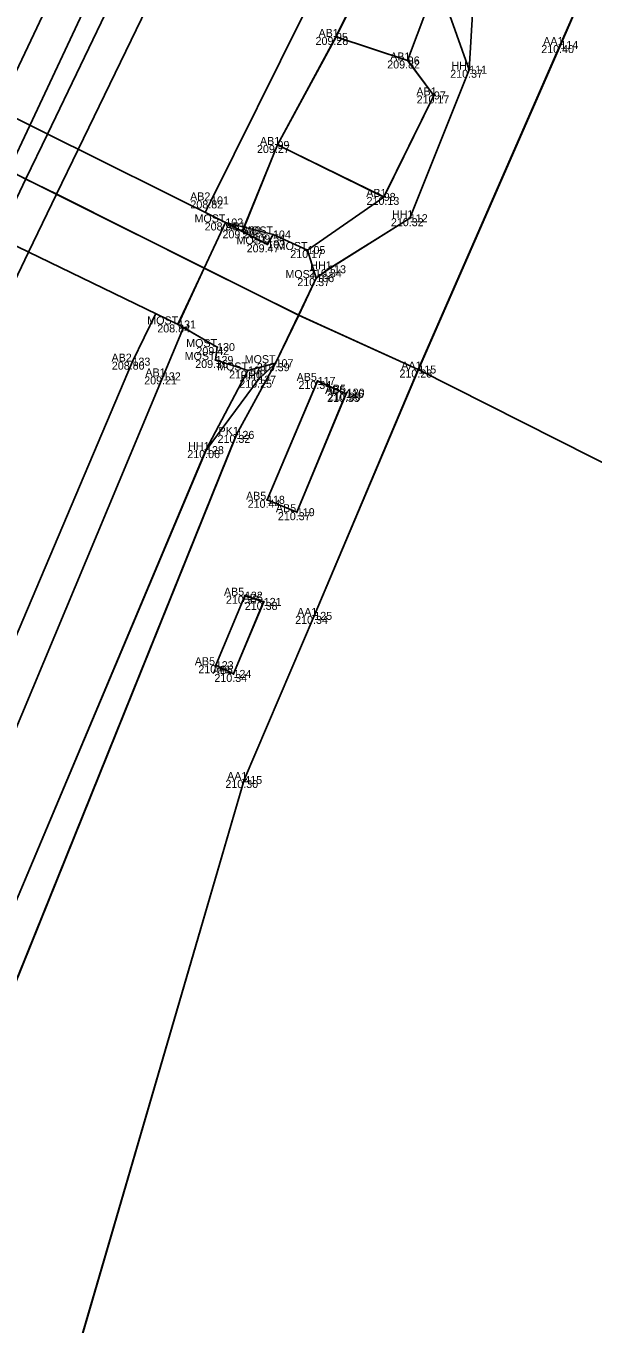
# Model space of a CAD drawing. Extents: x -262982 to -262706, y -1238714 to -1237093.
# Drawn here: x -262787.74 to -262773.56, y -1237705.27 to -1237672.82 of the extents above; entities that cross this region are included whole.
import ezdxf

# ---------------------------------------------------------------- set-up
doc = ezdxf.new("R2010")
doc.units = 0
for name, color, linetype in [('01_Hrana_betónu', 7, 'Continuous'), ('02_Oplotenie', 7, 'Continuous'), ('03_Asfalt', 7, 'Continuous'), ('04_Most', 7, 'Continuous'), ('05_Hrana_terénu', 7, 'Continuous'), ('07_Iné', 7, 'Continuous'), ('08_Mimo_zelene', 7, 'Continuous'), ('10', 7, 'Continuous'), ('Groma (21)', 7, 'Continuous'), ('Groma (22)', 7, 'Continuous'), ('Groma (23)', 7, 'Continuous'), ('Groma (24)', 7, 'Continuous'), ('U004_Betónové_panely', 7, 'Continuous'), ('U004_Ostatné_plochy', 7, 'Continuous'), ('U004_Zeleň_mimo', 7, 'Continuous'), ('U004_Zeleň_vnútro', 7, 'Continuous'), ('U004_Zeleň_zatrávňovač', 7, 'Continuous'), ('U005_Betónové_panely', 7, 'Continuous'), ('U005_Betóny_prídavné', 7, 'Continuous'), ('U005_Ostatné_plochy', 7, 'Continuous'), ('U005_Zeleň_mimo', 7, 'Continuous'), ('U005_Zeleň_vnútro', 7, 'Continuous'), ('U005_Zeleň_zatrávňovač', 7, 'Continuous')]:
    doc.layers.add(name, color=color, linetype=linetype)

msp = doc.modelspace()

# ---------------------------------------------------------------- linework, layer by layer
at = {"layer": '01_Hrana_betónu'}
for p, q in [((-262783.282, -1237678.876), (-262782.754, -1237677.736)), ((-262783.935, -1237680.285), (-262783.282, -1237678.876))]:
    msp.add_line(p, q, dxfattribs=at)
for points in [[(-262786.432, -1237675.911), (-262784.052, -1237670.991), (-262777.997, -1237658.39), (-262770.22, -1237641.884), (-262760.517, -1237621.621), (-262751.199, -1237602.266), (-262746.917, -1237592.345), (-262743.67, -1237583.59), (-262741.234, -1237574.416), (-262739.924, -1237566.213), (-262738.929, -1237556.596), (-262738.741, -1237547.665), (-262738.506, -1237524.618), (-262738.316, -1237501.393), (-262738.103, -1237478.98), (-262737.841, -1237459.175), (-262737.82, -1237425.07), (-262737.772, -1237401.714), (-262737.893, -1237377.738), (-262738.012, -1237356.488), (-262737.973, -1237332.295), (-262738.006, -1237318.022), (-262737.947, -1237310.645)], [(-262738.855, -1237311.192), (-262738.946, -1237318.051), (-262738.849, -1237332.413), (-262738.867, -1237356.312), (-262738.748, -1237377.69), (-262738.758, -1237401.69), (-262738.753, -1237425.185), (-262738.668, -1237459.096), (-262739.01, -1237478.875), (-262739.257, -1237501.361), (-262739.436, -1237524.506), (-262739.635, -1237547.624), (-262739.863, -1237556.5), (-262740.784, -1237566.075), (-262742.123, -1237574.161), (-262744.555, -1237583.315), (-262747.793, -1237592.067), (-262752.033, -1237601.877), (-262761.381, -1237621.164), (-262771.059, -1237641.465), (-262778.806, -1237657.918), (-262784.861, -1237670.667), (-262787.201, -1237675.529)], [(-262739.343, -1237311.485), (-262739.423, -1237318.909), (-262739.337, -1237332.42), (-262739.334, -1237355.849), (-262739.135, -1237377.701), (-262739.178, -1237401.786), (-262739.257, -1237424.031), (-262739.458, -1237458.924), (-262739.421, -1237479.296), (-262739.718, -1237500.116), (-262739.917, -1237524.824), (-262740.163, -1237546.913), (-262740.342, -1237556.649), (-262741.144, -1237564.78), (-262742.646, -1237573.838), (-262744.715, -1237582.455), (-262748.007, -1237591.229), (-262752.529, -1237601.669), (-262761.584, -1237620.386), (-262771.44, -1237641.076), (-262779.114, -1237657.574), (-262785.318, -1237670.364), (-262787.643, -1237675.31)], [(-262788.441, -1237674.914), (-262786.102, -1237669.974), (-262779.96, -1237657.146), (-262772.255, -1237640.671), (-262762.405, -1237620.082), (-262753.353, -1237601.237), (-262748.855, -1237590.92), (-262745.54, -1237582.117), (-262743.431, -1237573.688), (-262742.016, -1237564.7), (-262741.168, -1237556.501), (-262740.979, -1237546.892), (-262740.851, -1237524.752), (-262740.671, -1237500.08), (-262740.394, -1237479.483), (-262740.216, -1237458.955), (-262740.117, -1237423.647), (-262740.094, -1237401.75), (-262740.13, -1237377.708), (-262740.243, -1237355.929), (-262740.317, -1237332.345), (-262740.44, -1237318.894), (-262740.323, -1237312.076)], [(-262783.258, -1237677.486), (-262783.111, -1237677.185), (-262780.8, -1237672.534), (-262774.552, -1237659.911), (-262766.786, -1237643.656), (-262757.035, -1237623.248), (-262747.974, -1237603.808), (-262743.592, -1237593.531), (-262740.333, -1237584.524), (-262737.7, -1237574.963), (-262736.283, -1237566.732), (-262735.575, -1237556.629), (-262735.369, -1237547.722), (-262734.981, -1237524.159), (-262734.838, -1237501.704)], [(-262782.326, -1237677.959), (-262781.45, -1237675.8), (-262779.987, -1237673.099), (-262773.679, -1237660.319), (-262765.958, -1237644.106), (-262756.238, -1237623.625), (-262747.207, -1237604.197), (-262742.811, -1237593.79), (-262739.484, -1237584.835), (-262736.846, -1237575.127), (-262735.426, -1237566.88), (-262734.686, -1237556.753), (-262734.467, -1237547.755), (-262734.294, -1237524.216), (-262733.894, -1237501.859)], [(-262787.643, -1237675.31), (-262788.171, -1237676.433)], [(-262787.201, -1237675.529), (-262787.74, -1237676.649)], [(-262786.974, -1237677.031), (-262786.432, -1237675.911)], [(-262787.74, -1237676.649), (-262788.441, -1237678.106)], [(-262787.674, -1237678.477), (-262786.974, -1237677.031)], [(-262825.987, -1237933.123), (-262825.899, -1237930.36), (-262825.137, -1237919.703), (-262824.89, -1237915.193), (-262824.65, -1237906.715), (-262823.596, -1237885.855), (-262822.137, -1237871.403), (-262820.061, -1237857.781), (-262817.692, -1237845.812), (-262814.459, -1237830.149), (-262809.645, -1237808.205), (-262805.191, -1237787.117), (-262803.484, -1237767.641), (-262802.568, -1237744.998), (-262802.266, -1237722.317), (-262800.862, -1237712.121), (-262798.805, -1237704.616), (-262795.791, -1237696.17), (-262788.393, -1237679.964), (-262787.674, -1237678.477)], [(-262785.076, -1237681.215), (-262784.491, -1237680.016)], [(-262783.803, -1237680.361), (-262791.072, -1237697.733), (-262794.156, -1237706.196), (-262796.111, -1237713.494), (-262797.353, -1237722.795), (-262798.006, -1237745.028), (-262798.995, -1237767.834), (-262800.837, -1237788.066), (-262805.174, -1237808.895), (-262810.048, -1237831.05), (-262813.207, -1237846.368), (-262815.438, -1237858.025), (-262817.519, -1237871.503), (-262819.01, -1237885.889), (-262819.761, -1237906.843), (-262819.991, -1237915.564)], [(-262820.488, -1237916.085), (-262820.893, -1237915.574), (-262820.599, -1237906.725), (-262819.894, -1237885.916), (-262818.364, -1237871.361), (-262816.365, -1237858.042), (-262814.122, -1237846.343), (-262810.891, -1237830.85), (-262806.137, -1237808.69), (-262801.736, -1237787.923), (-262799.952, -1237767.772), (-262798.979, -1237744.912), (-262798.159, -1237722.635), (-262796.927, -1237713.21), (-262795.035, -1237705.927), (-262791.963, -1237697.425), (-262785.076, -1237681.215)]]:
    msp.add_lwpolyline(points, dxfattribs=at)
at = {"layer": '02_Oplotenie'}
msp.add_lwpolyline([(-262782.476, -1237683.046), (-262789.338, -1237700.035), (-262791.92, -1237707.468), (-262793.68, -1237714.792), (-262794.853, -1237723.195), (-262795.698, -1237745.299), (-262796.564, -1237768.081), (-262798.719, -1237788.188), (-262802.852, -1237809.448), (-262807.527, -1237831.589), (-262810.764, -1237846.834), (-262812.842, -1237857.763), (-262814.888, -1237871.127), (-262816.319, -1237886.182), (-262816.945, -1237895.233), (-262817.687, -1237906.993), (-262818.366, -1237915.571), (-262818.764, -1237925.136)], dxfattribs=at)
at = {"layer": '03_Asfalt'}
for points in [[(-262724.746, -1237307.401), (-262727.828, -1237308.991), (-262728.093, -1237318.612), (-262728.491, -1237332.383), (-262729.117, -1237356.253), (-262729.803, -1237378.892), (-262730.272, -1237401.612), (-262730.633, -1237425.617), (-262730.625, -1237458.196), (-262731.018, -1237478.61), (-262730.917, -1237502.542), (-262731.001, -1237524.284), (-262731.468, -1237547.904), (-262731.892, -1237556.788), (-262732.535, -1237567.203), (-262733.679, -1237576.214), (-262736.504, -1237586.306), (-262740.104, -1237594.868), (-262744.783, -1237605.686), (-262753.189, -1237625.134), (-262761.527, -1237644.232), (-262769.984, -1237663.306), (-262774.379, -1237673.302), (-262777.928, -1237681.411)], [(-262777.928, -1237681.411), (-262780.531, -1237687.57), (-262782.281, -1237691.672), (-262786.624, -1237706.531), (-262791.645, -1237746.487), (-262793.969, -1237766.446), (-262796.149, -1237782.824), (-262801.035, -1237810.714), (-262803.747, -1237825.804), (-262807.32, -1237845.566), (-262809.566, -1237858.112), (-262812.403, -1237873.547), (-262813.944, -1237886.41), (-262814.5, -1237895.481), (-262816.945, -1237895.233)]]:
    msp.add_lwpolyline(points, dxfattribs=at)
at = {"layer": '04_Most'}
for points in [[(-262794.832, -1237673.105), (-262794.423, -1237672.239), (-262794.016, -1237671.765), (-262792.919, -1237672.236), (-262791.945, -1237673.175), (-262782.754, -1237677.736), (-262781.704, -1237678.283), (-262781.563, -1237678.037), (-262780.7, -1237678.426), (-262780.481, -1237679.127), (-262780.925, -1237680.054)], [(-262780.925, -1237680.054), (-262781.499, -1237681.254), (-262782.189, -1237681.436), (-262783, -1237681.174), (-262782.961, -1237680.851), (-262783.935, -1237680.285), (-262793.299, -1237675.758), (-262794.227, -1237675.288), (-262794.619, -1237675.515), (-262795.493, -1237674.504), (-262794.832, -1237673.105)]]:
    msp.add_lwpolyline(points, dxfattribs=at)
at = {"layer": '05_Hrana_terénu'}
for points in [[(-262780.481, -1237679.127), (-262780.184, -1237678.906), (-262778.142, -1237677.63), (-262776.658, -1237673.919), (-262777.447, -1237671.687), (-262772.207, -1237661.172), (-262764.249, -1237644.683), (-262754.484, -1237624.262), (-262745.614, -1237605.143), (-262741.062, -1237594.471), (-262737.644, -1237585.61), (-262735.075, -1237575.555), (-262733.583, -1237567.143), (-262732.968, -1237556.742), (-262732.631, -1237547.918), (-262732.158, -1237524.14), (-262732.188, -1237502.434)], [(-262819.123, -1237925.833), (-262819.193, -1237924.361), (-262818.874, -1237915.472), (-262818.289, -1237906.84), (-262817.033, -1237886.241), (-262815.506, -1237871.209), (-262813.693, -1237857.604), (-262811.493, -1237846.649), (-262808.389, -1237831.401), (-262803.328, -1237809.401), (-262799.108, -1237788.219), (-262797.264, -1237767.972), (-262796.32, -1237745.233), (-262795.609, -1237723.113), (-262794.587, -1237714.488), (-262792.775, -1237707.13), (-262790.198, -1237699.936), (-262783.238, -1237683.427), (-262781.933, -1237681.667), (-262781.499, -1237681.254)]]:
    msp.add_lwpolyline(points, dxfattribs=at)
at = {"layer": '07_Iné'}
msp.add_lwpolyline([(-262781.45, -1237675.8), (-262778.794, -1237677.098), (-262777.541, -1237674.561), (-262778.195, -1237673.687), (-262779.987, -1237673.099)], dxfattribs=at)
at = {"layer": '08_Mimo_zelene'}
for points in [[(-262781.713, -1237684.669), (-262780.448, -1237681.698), (-262779.738, -1237682.023), (-262780.967, -1237684.978)], [(-262782.55, -1237689.021), (-262782.994, -1237688.803), (-262782.266, -1237687.066), (-262781.795, -1237687.221)]]:
    msp.add_lwpolyline(points, close=True, dxfattribs=at)
at = {"layer": '10'}
msp.add_lwpolyline([(-262813.033, -1237664.011), (-262780.925, -1237680.054), (-262777.93, -1237681.41), (-262750.961, -1237695.025)], dxfattribs=at)
at = {"layer": 'Groma (21)'}
for centre in [(-262779.987, -1237673.099), (-262774.379, -1237673.302), (-262778.195, -1237673.687), (-262776.658, -1237673.919), (-262777.541, -1237674.561), (-262781.45, -1237675.8), (-262783.111, -1237677.185), (-262778.794, -1237677.098), (-262778.142, -1237677.63), (-262782.754, -1237677.736), (-262782.315, -1237677.933), (-262781.563, -1237678.037), (-262781.704, -1237678.283), (-262780.7, -1237678.426), (-262780.184, -1237678.906), (-262780.481, -1237679.127), (-262783.935, -1237680.285), (-262782.961, -1237680.851), (-262785.076, -1237681.215), (-262783, -1237681.174), (-262781.499, -1237681.254), (-262784.315, -1237681.584), (-262782.189, -1237681.436), (-262777.928, -1237681.412), (-262781.933, -1237681.667), (-262780.448, -1237681.698), (-262779.738, -1237682.023), (-262779.72, -1237681.99), (-262782.476, -1237683.046), (-262783.238, -1237683.427), (-262781.713, -1237684.669), (-262780.967, -1237684.978), (-262782.266, -1237687.066), (-262781.795, -1237687.221), (-262780.531, -1237687.57), (-262782.994, -1237688.803), (-262782.55, -1237689.021), (-262782.281, -1237691.672)]:
    msp.add_circle(centre, 0.01, dxfattribs=at)
at = {"layer": 'U004_Betónové_panely'}
msp.add_lwpolyline([(-262809.47, -1237744.21), (-262809.35, -1237719.32), (-262807.76, -1237709.13), (-262805.58, -1237701.26), (-262801.1, -1237689.83), (-262795.06, -1237676.27), (-262794.18, -1237676.61), (-262793.3, -1237675.76), (-262792.52, -1237674.26), (-262788.97, -1237676.03), (-262788.17, -1237676.43), (-262787.74, -1237676.65), (-262786.97, -1237677.03), (-262783.28, -1237678.88), (-262783.94, -1237680.28), (-262783.8, -1237680.36), (-262791.07, -1237697.73), (-262794.16, -1237706.2), (-262796.11, -1237713.49), (-262797.35, -1237722.8), (-262798.01, -1237745.03)], dxfattribs=at)
at = {"layer": 'U004_Ostatné_plochy'}
for points in [[(-262783.94, -1237680.28), (-262783.28, -1237678.88), (-262780.92, -1237680.05), (-262781.5, -1237681.25), (-262782.19, -1237681.44), (-262783, -1237681.17), (-262782.96, -1237680.85)], [(-262781.71, -1237684.67), (-262780.45, -1237681.7), (-262779.74, -1237682.02), (-262780.97, -1237684.98)], [(-262781.8, -1237687.22), (-262782.55, -1237689.02), (-262782.99, -1237688.8), (-262782.27, -1237687.07)]]:
    msp.add_lwpolyline(points, close=True, dxfattribs=at)
at = {"layer": 'U004_Zeleň_mimo'}
msp.add_lwpolyline([(-262802.85, -1237809.45), (-262798.72, -1237788.19), (-262796.56, -1237768.08), (-262795.7, -1237745.3), (-262794.85, -1237723.2), (-262793.68, -1237714.79), (-262791.92, -1237707.47), (-262789.34, -1237700.03), (-262782.48, -1237683.05), (-262781.5, -1237681.25), (-262780.92, -1237680.05), (-262777.93, -1237681.41), (-262780.53, -1237687.57), (-262782.28, -1237691.67), (-262786.62, -1237706.53), (-262791.65, -1237746.49), (-262793.97, -1237766.45), (-262796.15, -1237782.82), (-262801.03, -1237810.71)], dxfattribs=at)
for points in [[(-262780.97, -1237684.98), (-262779.74, -1237682.02), (-262780.45, -1237681.7), (-262781.71, -1237684.67)], [(-262781.8, -1237687.22), (-262782.27, -1237687.07), (-262782.99, -1237688.8), (-262782.55, -1237689.02)]]:
    msp.add_lwpolyline(points, close=True, dxfattribs=at)
at = {"layer": 'U004_Zeleň_vnútro'}
msp.add_lwpolyline([(-262803.33, -1237809.4), (-262799.11, -1237788.22), (-262797.26, -1237767.97), (-262796.32, -1237745.23), (-262795.61, -1237723.11), (-262794.59, -1237714.49), (-262792.78, -1237707.13), (-262790.2, -1237699.94), (-262783.24, -1237683.43), (-262782.19, -1237681.44), (-262781.5, -1237681.25), (-262782.48, -1237683.05), (-262789.34, -1237700.03), (-262791.92, -1237707.47), (-262793.68, -1237714.79), (-262794.85, -1237723.2), (-262795.7, -1237745.3), (-262796.56, -1237768.08), (-262798.72, -1237788.19), (-262802.85, -1237809.45)], dxfattribs=at)
at = {"layer": 'U004_Zeleň_zatrávňovač'}
msp.add_lwpolyline([(-262805.17, -1237808.9), (-262800.84, -1237788.07), (-262799, -1237767.83), (-262798.01, -1237745.03), (-262797.35, -1237722.8), (-262796.11, -1237713.49), (-262794.16, -1237706.2), (-262791.07, -1237697.73), (-262783.8, -1237680.36), (-262782.96, -1237680.85), (-262783, -1237681.17), (-262782.19, -1237681.44), (-262783.24, -1237683.43), (-262790.2, -1237699.94), (-262792.78, -1237707.13), (-262794.59, -1237714.49), (-262795.61, -1237723.11), (-262796.32, -1237745.23), (-262797.26, -1237767.97), (-262799.11, -1237788.22), (-262803.33, -1237809.4)], dxfattribs=at)
at = {"layer": 'U005_Betónové_panely'}
msp.add_lwpolyline([(-262773.68, -1237660.32), (-262779.99, -1237673.1), (-262781.45, -1237675.8), (-262782.33, -1237677.96), (-262782.75, -1237677.74), (-262783.28, -1237678.88), (-262786.97, -1237677.03), (-262787.74, -1237676.65), (-262788.17, -1237676.43), (-262788.97, -1237676.03), (-262792.52, -1237674.26), (-262791.95, -1237673.18), (-262792.03, -1237673.09), (-262792.68, -1237672.47)], dxfattribs=at)
at = {"layer": 'U005_Betóny_prídavné'}
msp.add_lwpolyline([(-262778.2, -1237673.69), (-262777.54, -1237674.56), (-262778.79, -1237677.1), (-262781.45, -1237675.8), (-262779.99, -1237673.1)], close=True, dxfattribs=at)
at = {"layer": 'U005_Ostatné_plochy'}
msp.add_lwpolyline([(-262783.28, -1237678.88), (-262782.75, -1237677.74), (-262781.56, -1237678.04), (-262780.7, -1237678.43), (-262780.48, -1237679.13), (-262780.92, -1237680.05)], close=True, dxfattribs=at)
at = {"layer": 'U005_Zeleň_mimo'}
msp.add_lwpolyline([(-262769.98, -1237663.31), (-262774.38, -1237673.3), (-262777.93, -1237681.41), (-262780.92, -1237680.05), (-262780.48, -1237679.13), (-262780.18, -1237678.91), (-262778.14, -1237677.63), (-262776.66, -1237673.92), (-262776.48, -1237670.97)], dxfattribs=at)
at = {"layer": 'U005_Zeleň_vnútro'}
msp.add_lwpolyline([(-262776.48, -1237670.97), (-262776.66, -1237673.92), (-262778.14, -1237677.63), (-262780.18, -1237678.91), (-262780.48, -1237679.13), (-262780.7, -1237678.43), (-262778.79, -1237677.1), (-262777.54, -1237674.56), (-262778.2, -1237673.69), (-262777.45, -1237671.69)], dxfattribs=at)
at = {"layer": 'U005_Zeleň_zatrávňovač'}
msp.add_lwpolyline([(-262777.45, -1237671.69), (-262778.2, -1237673.69), (-262779.99, -1237673.1), (-262773.68, -1237660.32)], dxfattribs=at)
msp.add_lwpolyline([(-262781.56, -1237678.04), (-262781.7, -1237678.28), (-262782.33, -1237677.96), (-262781.45, -1237675.8), (-262778.79, -1237677.1), (-262780.7, -1237678.43)], close=True, dxfattribs=at)

# ---------------------------------------------------------------- texts
at = {"layer": 'Groma (22)'}
for s, p in [('95', (-262779.987, -1237673.199)), ('114', (-262774.379, -1237673.402)), ('96', (-262778.195, -1237673.787)), ('111', (-262776.658, -1237674.019)), ('97', (-262777.541, -1237674.661)), ('99', (-262781.45, -1237675.9)), ('98', (-262778.794, -1237677.198)), ('101', (-262783.111, -1237677.285)), ('102', (-262782.754, -1237677.836)), ('112', (-262778.142, -1237677.73)), ('100', (-262782.315, -1237678.033)), ('104', (-262781.563, -1237678.137)), ('103', (-262781.704, -1237678.383)), ('105', (-262780.7, -1237678.526)), ('113', (-262780.184, -1237679.006)), ('106', (-262780.481, -1237679.227)), ('131', (-262783.935, -1237680.385)), ('130', (-262782.961, -1237680.951)), ('133', (-262785.076, -1237681.315)), ('129', (-262783, -1237681.274)), ('107', (-262781.499, -1237681.354)), ('132', (-262784.315, -1237681.684)), ('108', (-262782.189, -1237681.536)), ('127', (-262781.933, -1237681.767)), ('117', (-262780.448, -1237681.798)), ('115', (-262777.928, -1237681.512)), ('116', (-262779.738, -1237682.123)), ('120', (-262779.72, -1237682.09)), ('126', (-262782.476, -1237683.146)), ('128', (-262783.238, -1237683.527)), ('118', (-262781.713, -1237684.769)), ('119', (-262780.967, -1237685.078)), ('122', (-262782.266, -1237687.166)), ('121', (-262781.795, -1237687.321)), ('125', (-262780.531, -1237687.67)), ('123', (-262782.994, -1237688.903)), ('124', (-262782.55, -1237689.121)), ('415', (-262782.281, -1237691.772))]:
    msp.add_text(s, height=0.2, dxfattribs=at).set_placement(p)
at = {"layer": 'Groma (23)'}
for s, p in [('209.28', (-262780.499, -1237673.299)), ('210.40', (-262774.856, -1237673.502)), ('209.82', (-262778.707, -1237673.887)), ('210.37', (-262777.132, -1237674.119)), ('210.17', (-262777.972, -1237674.761)), ('209.27', (-262781.963, -1237676)), ('208.82', (-262783.628, -1237677.385)), ('210.13', (-262779.224, -1237677.298)), ('210.32', (-262778.615, -1237677.83)), ('208.94', (-262783.271, -1237677.936)), ('209.28', (-262782.827, -1237678.133)), ('209.54', (-262782.08, -1237678.237)), ('209.47', (-262782.221, -1237678.483)), ('210.17', (-262781.131, -1237678.626)), ('210.34', (-262780.662, -1237679.106)), ('210.37', (-262780.955, -1237679.327)), ('208.84', (-262784.456, -1237680.485)), ('209.42', (-262783.478, -1237681.051)), ('208.80', (-262785.592, -1237681.415)), ('209.36', (-262783.507, -1237681.374)), ('210.39', (-262781.967, -1237681.454)), ('209.21', (-262784.783, -1237681.784)), ('210.20', (-262782.661, -1237681.636)), ('210.28', (-262778.401, -1237681.612)), ('210.25', (-262782.406, -1237681.867)), ('210.34', (-262780.926, -1237681.898)), ('210.35', (-262780.211, -1237682.223)), ('210.36', (-262780.188, -1237682.19)), ('210.32', (-262782.949, -1237683.246)), ('210.06', (-262783.706, -1237683.627)), ('210.44', (-262782.196, -1237684.869)), ('210.37', (-262781.441, -1237685.178)), ('210.37', (-262782.74, -1237687.266)), ('210.38', (-262782.268, -1237687.421)), ('210.34', (-262781.009, -1237687.77)), ('210.41', (-262783.429, -1237689.003)), ('210.34', (-262783.028, -1237689.221)), ('210.30', (-262782.753, -1237691.872))]:
    msp.add_text(s, height=0.2, dxfattribs=at).set_placement(p)
at = {"layer": 'Groma (24)'}
for s, p in [('AB1', (-262780.425, -1237673.099)), ('AA1', (-262774.807, -1237673.302)), ('AB1', (-262778.633, -1237673.687)), ('HH1', (-262777.105, -1237673.919)), ('AB1', (-262777.979, -1237674.561)), ('AB1', (-262781.888, -1237675.8)), ('AB2', (-262783.635, -1237677.185)), ('AB1', (-262779.232, -1237677.098)), ('MOST', (-262783.526, -1237677.736)), ('HH1', (-262778.589, -1237677.63)), ('AB1', (-262782.753, -1237677.933)), ('MOST', (-262782.335, -1237678.037)), ('MOST', (-262782.476, -1237678.283)), ('MOST', (-262781.472, -1237678.426)), ('MOST', (-262781.253, -1237679.127)), ('HH1', (-262780.631, -1237678.906)), ('MOST', (-262784.707, -1237680.285)), ('MOST', (-262783.733, -1237680.851)), ('AB2', (-262785.6, -1237681.215)), ('MOST', (-262783.772, -1237681.174)), ('MOST', (-262782.961, -1237681.436)), ('MOST', (-262782.271, -1237681.254)), ('AA1', (-262778.356, -1237681.412)), ('AB1', (-262784.753, -1237681.584)), ('HH1', (-262782.38, -1237681.667)), ('AB5', (-262780.972, -1237681.698)), ('AB5', (-262780.262, -1237682.023)), ('AB5', (-262780.244, -1237681.99)), ('PK1', (-262782.923, -1237683.046)), ('HH1', (-262783.685, -1237683.427)), ('AB5', (-262782.237, -1237684.669)), ('AB5', (-262781.491, -1237684.978)), ('AB5', (-262782.79, -1237687.066)), ('AB5', (-262782.319, -1237687.221)), ('AA1', (-262780.959, -1237687.57)), ('AB5', (-262783.518, -1237688.803)), ('AB5', (-262783.074, -1237689.021)), ('AA1', (-262782.709, -1237691.672))]:
    msp.add_text(s, height=0.2, dxfattribs=at).set_placement(p)

doc.saveas('drawing.dxf')
